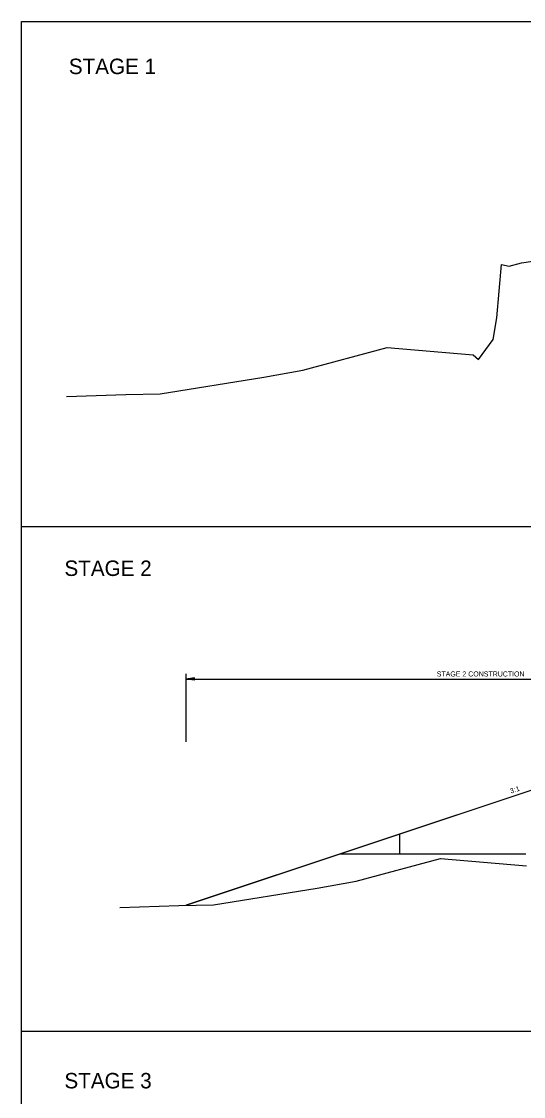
# Model space of a CAD drawing. Extents: x 2829243 to 2838161, y 467639 to 474695.
# Drawn here: x 2829486 to 2830081, y 468992 to 470266 of the extents above; entities that cross this region are included whole.
import ezdxf

# ---------------------------------------------------------------- set-up
doc = ezdxf.new("R2010")
doc.units = 0
for name, color, linetype in [('Default', 7, 'Continuous'), ('R_Dimension', 7, 'Continuous'), ('R_Draft', 7, 'Continuous'), ('R_Exist Surface', 7, 'Continuous'), ('R_Fin Surface', 7, 'Continuous'), ('R_Water', 7, 'Continuous')]:
    doc.layers.add(name, color=color, linetype=linetype)

msp = doc.modelspace()

# ---------------------------------------------------------------- linework, layer by layer
at = {"layer": 'Default'}
for p, q in [((2829486.2, 469667.7), (2831121.8, 469667.7)), ((2829486.2, 469069.4), (2831121.8, 469069.4))]:
    msp.add_line(p, q, dxfattribs=at)
msp.add_lwpolyline([(2829486.2, 470265.9), (2831121.8, 470265.9), (2831121.8, 468471.1), (2829486.2, 468471.1)], close=True, dxfattribs=at)
at = {"layer": 'R_Dimension'}
for p, q in [((2829681.3, 469412.3), (2829681.3, 469492.8)), ((2829691.3, 469488.3), (2829681.3, 469486.8)), ((2829691.3, 469488), (2829683, 469486.8)), ((2829691.3, 469487.7), (2829684.7, 469486.8)), ((2829691.3, 469485.3), (2829691.3, 469488.3)), ((2829681.3, 469486.8), (2830386.5, 469486.8)), ((2829691.3, 469485.3), (2829681.3, 469486.8)), ((2829691.3, 469485.5), (2829683, 469486.8)), ((2829691.3, 469485.8), (2829684.7, 469486.8)), ((2829691.3, 469487.5), (2829686.4, 469486.8)), ((2829691.3, 469486), (2829686.4, 469486.8)), ((2829691.3, 469487.2), (2829688, 469486.8)), ((2829691.3, 469486.3), (2829688, 469486.8)), ((2829691.3, 469487), (2829689.7, 469486.8)), ((2829691.3, 469486.5), (2829689.7, 469486.8))]:
    msp.add_line(p, q, dxfattribs=at)
at = {"layer": 'R_Draft'}
msp.add_line((2830136.5, 469370.4), (2829681.3, 469218.7), dxfattribs=at)
at = {"layer": 'R_Exist Surface'}
for points in [[(2829539.5, 469821.4), (2829609.7, 469823.9), (2829650.6, 469824.9), (2829773.5, 469844.4), (2829819.5, 469852.9), (2829919.5, 469879.7), (2830021.5, 469870.9), (2830028, 469865.5), (2830045.3, 469889), (2830049.5, 469914.7), (2830055.2, 469978), (2830064.2, 469975.9), (2830078.8, 469979.8), (2830175.8, 469994.1)], [(2829602.7, 469216), (2829672.8, 469218.5), (2829713.8, 469219.4), (2829836.7, 469239), (2829882.7, 469247.4), (2829982.7, 469274.3), (2830084.6, 469265.4)]]:
    msp.add_lwpolyline(points, dxfattribs=at)
at = {"layer": 'R_Fin Surface'}
msp.add_lwpolyline([(2829681.3, 469218.7), (2830136.5, 469370.4), (2830167.4, 469378.1), (2830173, 469379.5), (2830226.7, 469392.9), (2830236.5, 469395.4), (2830270.3, 469396.7), (2830276.5, 469397), (2830369.5, 469398.8), (2830386.5, 469399.2)], dxfattribs=at)
at = {"layer": 'R_Water'}
for p, q in [((2829934.3, 469303), (2829934.3, 469279.7)), ((2829864.4, 469279.7), (2830083.9, 469279.7))]:
    msp.add_line(p, q, dxfattribs=at)

# ---------------------------------------------------------------- texts
at = {"layer": 'R_Dimension'}
for s, height, p in [('STAGE 1', 18.31, (2829542.3, 470203.6)), ('STAGE 2', 18.31, (2829537.1, 469608.9)), ('STAGE 2 CONSTRUCTION', 6, (2829978.4, 469489.8)), ('STAGE 3', 18.31, (2829537.1, 469001.7))]:
    msp.add_text(s, height=height, dxfattribs=at).set_placement(p)
msp.add_text('3:1', height=6, rotation=18.4349, dxfattribs=at).set_placement((2830066.4, 469351))

doc.saveas('drawing.dxf')
